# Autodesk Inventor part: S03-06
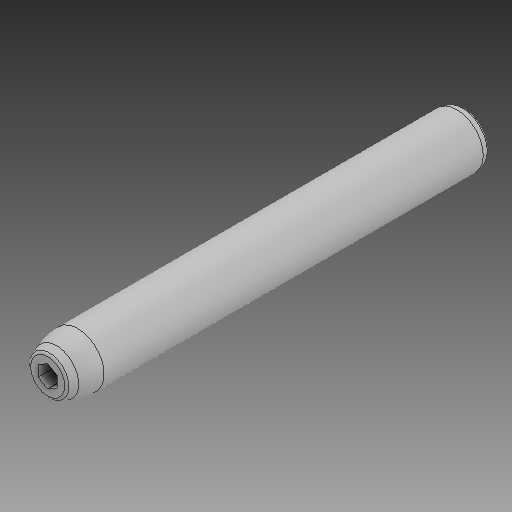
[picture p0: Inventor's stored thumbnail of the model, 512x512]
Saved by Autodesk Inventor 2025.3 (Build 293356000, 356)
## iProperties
Created: 2025-05
Part Number: S03-06
Material: Všeobecné
Document SubType Name: Modeling
Designer: Patrik
Density: 1 g/cm^3
Appearance: Výchozí
Mass: 16.1835 g
Surface Area: 54.0732 cm^2
Volume: 16.1835 cm^3
Description: Šikmý kolík bez nákružku
Stock Number: E 1034/14x110
User Status: 1.7131
Sending System: KiM GmbH
Major Version: 4.0
Minor Version: 0.0
Format Version: 0.0
Product Id: KiM GmbH
cc_prop_force_one_body: 1
Hersteller: Meusburger
Material: 1.7131 ~ 60 HRC
Bestellnummer: E 1034/14x110
Teilenummer: E 1034/14x110
Beschreibung: Schrägbolzen ohne Bund _ Inclined pin without collar
Author: Patrik
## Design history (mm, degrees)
feature "E 1034_14x110_1_1:1"
node "Těleso1"
